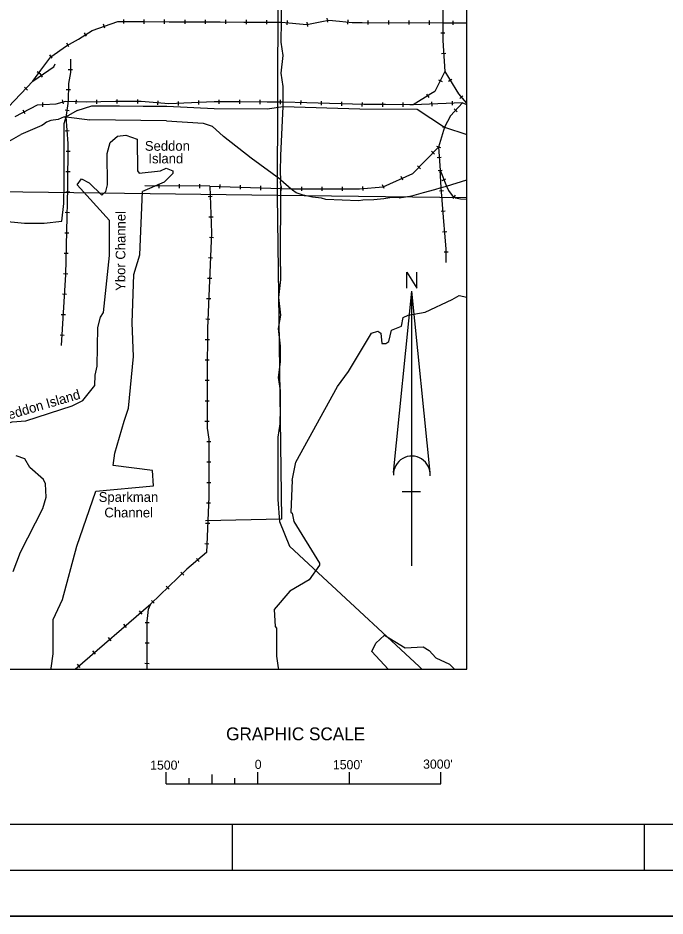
# Model space of a CAD drawing. Extents: x 492225 to 553725, y 1303773 to 1347273.
# Drawn here: x 511586 to 522187, y 1303773 to 1318479 of the extents above; entities that cross this region are included whole.
import ezdxf

# ---------------------------------------------------------------- set-up
doc = ezdxf.new("R2010")
doc.units = 0
for name, color, linetype in [('G-ANNO-TTLB', 7, 'Continuous'), ('Level 1', 7, 'Continuous'), ('Level 2', 7, 'Continuous'), ('Level 22', 7, 'Continuous'), ('Level 37', 7, 'Continuous'), ('Level 41', 7, 'Continuous'), ('Level 5', 7, 'Continuous'), ('Level 52', 7, 'Continuous')]:
    doc.layers.add(name, color=color, linetype=linetype)

msp = doc.modelspace()

# ---------------------------------------------------------------- linework, layer by layer
at = {"layer": 'G-ANNO-TTLB'}
for p, q in [((552225.069, 1305272.564), (494850.069, 1305272.564)), ((515100.069, 1304522.564), (515100.069, 1305272.564)), ((521850.069, 1304522.564), (521850.069, 1305272.564)), ((492975.069, 1304522.564), (552975.069, 1304522.564))]:
    msp.add_line(p, q, dxfattribs=at)
for points in [[(492225.069, 1303772.564), (553725.069, 1303772.564), (553725.069, 1347272.564), (492225.069, 1347272.564)], [(492225.069, 1303772.564), (553725.069, 1303772.564), (553725.069, 1347272.564), (492225.069, 1347272.564)], [(492225.069, 1347272.564), (553725.069, 1347272.564), (553725.069, 1303772.564), (492225.069, 1303772.564)]]:
    msp.add_lwpolyline(points, close=True, dxfattribs=at)
at = {"layer": 'Level 1'}
for p, q in [((515845.848, 1320879.851), (515834.762, 1315574.291)), ((515834.762, 1315574.291), (510479.1, 1315638.587)), ((518939.561, 1315533.3989), (515834.762, 1315574.291)), ((515834.762, 1315574.291), (515901.787, 1310274.027)), ((515901.787, 1310274.027), (514658.533, 1310245.241)), ((514014.882, 1305939.614), (514014.897, 1306127.669)), ((514764.897, 1305939.614), (514764.897, 1306092.989)), ((515514.897, 1305939.614), (515514.882, 1306127.654)), ((515514.897, 1305939.614), (515514.882, 1306127.654)), ((517014.897, 1305939.599), (517014.912, 1306127.654)), ((518514.912, 1305939.599), (518514.897, 1306127.654)), ((514014.882, 1305939.614), (518515.272, 1305939.614)), ((514389.882, 1305943.364), (514389.897, 1306029.614)), ((514764.882, 1305943.364), (514764.882, 1306029.614)), ((515139.897, 1305943.364), (515139.897, 1306029.614)), ((515514.897, 1305939.614), (515514.912, 1306029.599))]:
    msp.add_line(p, q, dxfattribs=at)
at = {"layer": 'Level 2'}
for p, q in [((517739.691, 1311035.137), (518038.191, 1314005.137)), ((518038.191, 1309505.137), (518038.191, 1314005.137)), ((518336.691, 1311035.137), (518038.191, 1314005.137)), ((518180.361, 1310720.377), (517880.376, 1310720.377))]:
    msp.add_line(p, q, dxfattribs=at)
msp.add_lwpolyline([(517955.226, 1314053.272), (517955.226, 1314315.772), (518118.516, 1314053.272), (518118.516, 1314315.772)], dxfattribs=at)
msp.add_arc((518038.1908, 1311005.1371), 300, 355.29842222, 182.06726111, dxfattribs=at)
at = {"layer": 'Level 22'}
for p, q in [((515901.462, 1318410.756), (515902.238, 1318628.886)), ((515900.557, 1318156.271), (515901.283, 1318360.223)), ((515901.283, 1318360.223), (515901.462, 1318410.756)), ((515900.299, 1318083.561), (515900.557, 1318156.271)), ((515931.806, 1317865.317), (515900.299, 1318083.561)), ((515898.489, 1317574.591), (515931.806, 1317865.317)), ((515929.997, 1317356.347), (515898.489, 1317574.591)), ((515929.092, 1317101.863), (515929.997, 1317356.347)), ((512554.316, 1316963.462), (512797.369, 1317040.381)), ((512797.369, 1317040.381), (513249.333, 1317038.744)), ((513249.333, 1317038.744), (513636.73, 1317037.347)), ((513636.73, 1317037.347), (514024.129, 1317035.952)), ((514024.129, 1317035.952), (514798.794, 1316996.819)), ((514798.794, 1316996.819), (515670.439, 1316993.714)), ((515670.439, 1316993.714), (515928.834, 1317029.152)), ((515893.707, 1316229.457), (515928.834, 1317029.152)), ((515928.834, 1317029.152), (515929.092, 1317101.863)), ((515928.834, 1317029.152), (517187.748, 1316988.353)), ((517187.748, 1316988.353), (518123.959, 1316985.073)), ((518123.959, 1316985.073), (518574.909, 1316692.659)), ((512340.857, 1316857.353), (512377.025, 1316860.129)), ((512344.344, 1316751.182), (512377.025, 1316860.129)), ((512554.316, 1316963.462), (512377.025, 1316860.129)), ((512377.025, 1316860.129), (512764.245, 1316809.28)), ((511978.774, 1316719.066), (511633.444, 1316571.996)), ((512343.284, 1316460.342), (512344.344, 1316751.182)), ((514019.379, 1316793.115), (512764.245, 1316809.28)), ((514765.469, 1316706.095), (514953.41, 1316539.643)), ((518574.909, 1316692.659), (518939.561, 1316570.4755)), ((511439.343, 1316463.639), (511633.444, 1316571.996)), ((515406.697, 1316183.198), (514953.41, 1316539.643)), ((512340.767, 1315769.597), (512343.284, 1316460.342)), ((515890.984, 1315826.649), (515406.697, 1316183.198)), ((515886.315, 1315966.271), (515893.707, 1316229.457)), ((515890.984, 1315826.649), (515886.315, 1315966.271)), ((515885.674, 1315785.95), (515890.984, 1315826.649)), ((515890.984, 1315826.649), (516060.929, 1315680.625)), ((518607.702, 1315727.31), (518939.561, 1315826.5473)), ((512339.574, 1315442.402), (512340.767, 1315769.597)), ((515895.778, 1315721.928), (515885.674, 1315785.95)), ((515890.994, 1315466.003), (515891.769, 1315684.133)), ((515891.769, 1315684.133), (515895.778, 1315721.928)), ((518519.797, 1315701.077), (518607.702, 1315727.31)), ((516629.419, 1315508.989), (516561.444, 1315527.617)), ((517165.664, 1315484.771), (516629.419, 1315508.989)), ((512306.229, 1315151.679), (512339.574, 1315442.402)), ((515890.089, 1315211.519), (515890.994, 1315466.003)), ((515889.184, 1314957.034), (515890.089, 1315211.519)), ((511305.404, 1315155.333), (511692.687, 1315117.561)), ((511692.687, 1315117.561), (512015.535, 1315116.383)), ((512015.535, 1315116.383), (512306.229, 1315151.679)), ((515888.28, 1314702.549), (515889.184, 1314957.034)), ((515887.247, 1314411.71), (515888.28, 1314702.549)), ((515887.247, 1314411.71), (515886.471, 1314193.58)), ((515886.471, 1314193.58), (515853.152, 1313902.856)), ((515853.152, 1313902.856), (515884.404, 1313611.902)), ((515884.404, 1313611.902), (515851.343, 1313393.887)), ((515851.343, 1313393.887), (515882.596, 1313102.933)), ((515882.596, 1313102.933), (515881.691, 1312848.448)), ((515881.691, 1312848.448), (515848.5, 1312594.078)), ((515848.5, 1312594.078), (515880.012, 1312375.834)), ((515880.012, 1312375.834), (515878.979, 1312084.995)), ((515878.979, 1312084.995), (515878.074, 1311830.51)), ((515878.074, 1311830.51), (515845.011, 1311612.496)), ((515845.011, 1311612.496), (515844.237, 1311394.367)), ((515844.237, 1311394.367), (515843.849, 1311285.302)), ((515843.849, 1311285.302), (515843.203, 1311103.528)), ((515843.203, 1311103.528), (515842.428, 1310885.398)), ((515842.428, 1310885.398), (515841.781, 1310703.624)), ((515841.781, 1310703.624), (515841.394, 1310594.559)), ((515841.394, 1310594.559), (515872.391, 1310230.896)), ((516579.529, 1309319.512), (518156.631, 1307859.771)), ((518156.631, 1307859.771), (518201.4251, 1307817.676))]:
    msp.add_line(p, q, dxfattribs=at)
for points in [[(512340.857, 1316857.353), (512242.568, 1316816.992), (512123.702, 1316799.973), (512051.28, 1316771.153), (512004.664, 1316736.422), (511978.774, 1316719.066)], [(514019.379, 1316793.115), (514618.434, 1316756.065), (514765.469, 1316706.095)], [(516561.444, 1315527.617), (516411.707, 1315545.597), (516256.845, 1315575.228), (516143.349, 1315616.348), (516081.508, 1315657.284), (516060.929, 1315680.625)], [(517832.197, 1315534.786), (518038.939, 1315568.964), (518230.245, 1315620.649), (518416.385, 1315672.352), (518519.797, 1315701.077)], [(517832.197, 1315534.786), (517713.412, 1315541.018), (517579.027, 1315518.222), (517413.669, 1315501.35), (517238.022, 1315496.15), (517165.664, 1315484.771)], [(515872.391, 1310230.896), (516032.415, 1309830.42), (516579.529, 1309319.512)]]:
    msp.add_lwpolyline(points, dxfattribs=at)
at = {"layer": 'Level 37'}
for p, q in [((513318.309, 1318386.333), (513318.551, 1318453.674)), ((513653.159, 1318385.123), (513653.402, 1318452.466)), ((513988.009, 1318383.919), (513988.252, 1318451.261)), ((514322.86, 1318382.717), (514323.102, 1318450.058)), ((514657.71, 1318381.517), (514657.952, 1318448.858)), ((514992.561, 1318380.319), (514992.803, 1318447.662)), ((515327.412, 1318379.125), (515327.652, 1318446.467)), ((515662.263, 1318377.934), (515662.503, 1318445.276)), ((516665.139, 1318407.758), (516651.826, 1318473.771)), ((516988.219, 1318380.164), (516994.748, 1318447.188)), ((517325.875, 1318372.059), (517326.112, 1318439.401)), ((513007.349, 1318311.232), (512985.532, 1318374.941)), ((515993.821, 1318368.617), (515999.871, 1318435.687)), ((516336.828, 1318341.75), (516323.571, 1318407.774)), ((517660.725, 1318370.888), (517660.962, 1318438.23)), ((517995.576, 1318369.718), (517995.813, 1318437.058)), ((518330.427, 1318368.547), (518330.663, 1318435.888)), ((518715.893, 1318367.202), (518716.128, 1318434.543)), ((512711.094, 1318178.559), (512674.859, 1318235.319)), ((518514.331, 1318234.145), (518581.671, 1318233.911)), ((512421.238, 1318007.243), (512388.411, 1318066.042)), ((512148.137, 1317819.6), (512109.579, 1317874.81)), ((518526.609, 1317897.538), (518593.829, 1317901.566)), ((511955.176, 1317560.346), (511900.42, 1317599.546)), ((511986.881, 1317512.068), (511948.324, 1317567.279)), ((512410.754, 1317637.82), (512478.095, 1317637.576)), ((518578.205, 1317637.888), (518578.079, 1317601.533)), ((511830.337, 1317443.808), (511432.356, 1317023.539)), ((518473.338, 1317466.643), (518533.625, 1317436.64)), ((518637.312, 1317441.355), (518694.629, 1317476.707)), ((511690.766, 1317345.391), (511739.663, 1317299.088)), ((512377.262, 1317305.929), (512444.603, 1317305.684)), ((512332.629, 1317070.595), (512315.277, 1317135.663)), ((512539.352, 1317140.429), (512536.439, 1317073.151)), ((512871.695, 1317137.513), (512873.384, 1317070.192)), ((513207.416, 1317145.278), (513207.172, 1317077.938)), ((513542.266, 1317144.069), (513542.022, 1317076.728)), ((513878.86, 1317120.917), (513873.219, 1317053.813)), ((514543.08, 1317127.971), (514546.132, 1317060.698)), ((514879.317, 1317139.269), (514879.075, 1317071.928)), ((515214.167, 1317138.074), (515213.926, 1317070.733)), ((515549.017, 1317136.883), (515548.777, 1317069.542)), ((515883.867, 1317135.693), (515883.628, 1317068.353)), ((516219.498, 1317126.616), (516217.427, 1317059.306)), ((516554.2, 1317116.24), (516552.108, 1317048.932)), ((518280.569, 1317232.219), (518315.639, 1317174.73)), ((518698.171, 1317118.244), (518700.967, 1317050.961)), ((518826.625, 1317159.26), (518877.134, 1317203.8)), ((511701.899, 1316909.996), (511671.037, 1316969.849)), ((511995.572, 1317026), (511991.289, 1317093.206)), ((514208.571, 1317112.794), (514211.623, 1317045.522)), ((516888.892, 1317105.832), (516886.798, 1317038.523)), ((517223.582, 1317095.424), (517221.489, 1317028.115)), ((517557.49, 1317093.437), (517557.254, 1317026.096)), ((517892.34, 1317092.265), (517892.104, 1317024.924)), ((518866.851, 1317091.554), (518059.648, 1317058.009)), ((518363.607, 1317104.341), (518366.403, 1317037.058)), ((518730.147, 1316989.194), (518780.344, 1316944.304)), ((512425.718, 1316956.809), (512359.141, 1316966.928)), ((518541.337, 1316697.928), (518605.842, 1316678.589)), ((512426.889, 1316631.108), (512359.713, 1316626.382)), ((512440.919, 1316294.274), (512373.579, 1316294.518)), ((518411.331, 1316249.71), (518362.964, 1316296.566)), ((518445.176, 1316377.177), (518509.681, 1316357.838)), ((518476.917, 1316365.802), (518501.421, 1315986.53)), ((518454.111, 1316196.552), (518521.312, 1316200.894)), ((512439.699, 1315959.421), (512372.358, 1315959.666)), ((518178.339, 1316009.204), (518129.973, 1316056.061)), ((518535.574, 1315980.131), (518468.371, 1315975.804)), ((517892.847, 1315821.463), (517865.406, 1315882.959)), ((518533.781, 1315818.845), (518596.089, 1315844.392)), ((514729.667, 1315724.627), (513664.288, 1315728.451)), ((513892.662, 1315761.303), (513892.419, 1315693.96)), ((514227.512, 1315760.1), (514227.269, 1315692.758)), ((514562.363, 1315758.898), (514562.12, 1315691.557)), ((514895.819, 1315685.145), (514898.164, 1315752.447)), ((515230.469, 1315673.484), (515232.814, 1315740.786)), ((515565.118, 1315661.823), (515567.463, 1315729.125)), ((515900.245, 1315650.278), (515901.642, 1315717.607)), ((516235.847, 1315647.403), (516235.674, 1315714.744)), ((516570.494, 1315648.061), (516570.732, 1315715.402)), ((516905.344, 1315646.881), (516905.582, 1315714.223)), ((517243.11, 1315651.182), (517237.054, 1315718.251)), ((517587.058, 1315685.008), (517559.616, 1315746.505)), ((518557.915, 1315646.538), (518490.786, 1315641.194)), ((512436.829, 1315623.827), (512369.512, 1315625.604)), ((514702.495, 1315556.021), (514769.787, 1315558.626)), ((518715.724, 1315521.947), (518752.114, 1315578.61)), ((512427.987, 1315289.088), (512360.669, 1315290.865)), ((514715.444, 1315221.417), (514782.735, 1315224.021)), ((518584.484, 1315312.738), (518517.356, 1315307.394)), ((512419.144, 1314954.349), (512351.827, 1314956.127)), ((518611.005, 1314978.926), (518543.875, 1314973.601)), ((514722.305, 1314889.643), (514789.579, 1314886.623)), ((512410.302, 1314619.61), (512342.984, 1314621.388)), ((518633.717, 1314642.206), (518566.375, 1314642.44)), ((514707.287, 1314555.124), (514774.56, 1314552.105)), ((512401.459, 1314284.872), (512334.142, 1314286.649)), ((514692.269, 1314220.606), (514759.542, 1314217.587)), ((512381.86, 1313949.492), (512314.637, 1313953.468)), ((514677.25, 1313886.088), (514744.524, 1313883.067)), ((512362.084, 1313615.221), (512294.861, 1313619.197)), ((514662.232, 1313551.569), (514729.505, 1313548.549)), ((512342.309, 1313280.949), (512275.084, 1313284.926)), ((514654.718, 1313215.478), (514722.059, 1313215.238)), ((514653.519, 1312880.625), (514720.859, 1312880.384)), ((514652.318, 1312545.772), (514719.659, 1312545.531)), ((514651.118, 1312210.918), (514718.459, 1312210.678)), ((514649.919, 1311876.065), (514717.259, 1311875.824)), ((514681.016, 1311543.942), (514748.356, 1311543.702)), ((514679.816, 1311209.088), (514747.157, 1311208.848)), ((514678.617, 1310874.235), (514745.958, 1310873.995)), ((514674.045, 1310540.65), (514741.336, 1310538.018)), ((514660.959, 1310206.05), (514728.248, 1310203.419)), ((514647.87, 1309871.451), (514715.16, 1309868.819)), ((514508.761, 1309628.178), (514552.402, 1309576.892)), ((514256.284, 1309405.391), (514302.873, 1309356.766)), ((514014.499, 1309173.728), (514061.089, 1309125.103)), ((512520.748, 1307817.676), (513763.26, 1308886.373)), ((513772.714, 1308942.063), (513819.303, 1308893.438)), ((513619.002, 1308717.884), (513575.091, 1308768.939)), ((513365.134, 1308499.529), (513321.222, 1308550.583)), ((513736.717, 1308574.809), (513669.376, 1308575.053)), ((513111.266, 1308281.174), (513067.354, 1308332.229)), ((513735.509, 1308239.957), (513668.168, 1308240.199)), ((512857.398, 1308062.819), (512813.485, 1308113.874)), ((512603.529, 1307844.465), (512559.618, 1307895.52)), ((513734.302, 1307905.103), (513666.96, 1307905.346))]:
    msp.add_line(p, q, dxfattribs=at)
for points in [[(518549.474, 1318655.94), (518548.585, 1318401.455)], [(511830.337, 1317443.808), (511960.133, 1317625.113), (512122.342, 1317842.654), (512381.265, 1318023.489), (512575.356, 1318131.851), (512801.86, 1318276.45), (513222.055, 1318420.351), (513641.721, 1318418.836), (514061.388, 1318417.326), (514448.771, 1318415.936), (514900.719, 1318414.319), (515288.104, 1318412.936), (515675.489, 1318411.558), (515901.462, 1318410.756), (516320.999, 1318372.914), (516566.519, 1318422.218), (516676.359, 1318444.37), (516854.496, 1318427.018), (517063.614, 1318406.651), (517225.024, 1318406.083), (518548.585, 1318401.455)], [(518548.585, 1318401.455), (518547.571, 1318110.615), (518578.079, 1317601.533)], [(518548.585, 1318401.455), (518939.561, 1318400.0967)], [(511830.337, 1317443.808), (512089.264, 1317624.642), (512131.967, 1317649.208), (512173.395, 1317678.142), (512194.246, 1317730.418)], [(512445.035, 1317805.124), (512444.24, 1317586.994), (512411.295, 1317405.337), (512410.228, 1317112.315)], [(518578.079, 1317601.533), (518415.522, 1317274.901), (518348.231, 1317234.053), (518059.648, 1317058.009)], [(518578.079, 1317601.533), (518757.849, 1317310.065), (518802.791, 1317237.198), (518931.417, 1317091.33)], [(511537.659, 1316863.189), (511908.006, 1317054.158), (511999.714, 1317060.003), (512212.511, 1317073.408), (512345.649, 1317108.914), (512369.562, 1317115.372), (512410.228, 1317112.315)], [(512298.809, 1313115.802), (512367.62, 1314278.927), (512405.071, 1315696.653), (512407.719, 1316423.752), (512377.025, 1316860.129), (512380.996, 1316886.654), (512410.104, 1317078.142), (512410.228, 1317112.315)], [(518059.648, 1317058.009), (518006.38, 1317058.195), (517607.684, 1317059.59), (517252.569, 1317060.835), (516316.452, 1317089.947), (515929.092, 1317101.863), (515670.828, 1317102.779), (515226.935, 1317104.358), (514896.034, 1317105.538), (514799.184, 1317105.885), (514056.543, 1317072.191), (513604.71, 1317110.173), (513185.03, 1317111.688), (512703.639, 1317099.617), (512410.228, 1317112.315)], [(518866.851, 1317091.554), (518672.392, 1316874.097), (518574.909, 1316692.659), (518476.917, 1316365.802)], [(518866.851, 1317091.554), (518939.561, 1317063.9721)], [(514729.667, 1315724.627), (515891.769, 1315684.133), (516060.929, 1315680.625), (516537.454, 1315681.848), (516559.408, 1315681.771), (517183.139, 1315679.574), (517570.677, 1315714.569), (518055.703, 1315931.006), (518476.917, 1316365.802)], [(518501.421, 1315986.53), (518607.702, 1315727.31), (518640.374, 1315653.395), (518698.208, 1315573.212), (518756.834, 1315535.563), (518837.478, 1315515.651), (518934.955, 1315509.495), (518939.561, 1315509.2535)], [(518599.463, 1314474.897), (518600.223, 1314693.026), (518578.561, 1314962.13), (518564.026, 1315145.412), (518519.797, 1315701.077), (518501.421, 1315986.53)], [(514729.667, 1315724.627), (514759.216, 1314961.058), (514689.043, 1313398.026), (514686.307, 1312634.573), (514683.441, 1311834.764), (514683.18, 1311762.054), (514714.816, 1311580.164), (514714.035, 1311362.035), (514713.123, 1311107.551), (514712.212, 1310853.067), (514711.429, 1310634.938), (514675.885, 1309726.181), (514352.972, 1309451.399), (513763.26, 1308886.373)], [(513700.3148, 1307817.676), (513703.146, 1308602.654), (513713.162, 1308693.871), (513724.184, 1308795.262), (513763.26, 1308886.373)]]:
    msp.add_lwpolyline(points, dxfattribs=at)
at = {"layer": 'Level 5'}
for points in [[(512938.391, 1313578.837), (512988.64, 1313653.698), (513083.079, 1314586.863), (513084.808, 1315161.936), (512553.169, 1315746.933), (512628.478, 1315846.714), (512753.298, 1315779.655), (512961.037, 1315579.027), (513027.887, 1315637.158), (513053.227, 1315745.428), (513046.436, 1316262.18), (513096.975, 1316437.062), (513213.954, 1316545.053), (513355.714, 1316561.315), (513538.864, 1316494.067), (513545.654, 1315977.314), (513570.504, 1315935.584), (513920.683, 1315976.218), (514012.483, 1316017.599), (514120.722, 1315975.63), (514120.562, 1315933.949), (513978.463, 1315792.678), (513627.954, 1315635.383)], [(513454.839, 1313485.612), (513482.228, 1314277.286), (513583.197, 1314602.048), (513627.954, 1315635.383)], [(517897.302, 1313572.366), (517979.246, 1313613.543), (518257.926, 1313660.016), (518697.382, 1313866.155), (518815.158, 1313936.337), (518939.561, 1313908.9071)], [(512852.213, 1312628.962), (512886.003, 1312778.903), (512896.211, 1313412.286), (512938.391, 1313578.837)], [(512863.206, 1310728.703), (513805.233, 1310817.563), (513789.303, 1311067.634), (513147.834, 1311152.918), (513173.434, 1311352.859), (513327.041, 1311876.715), (513395.55, 1312091.4), (513478.21, 1312935.489), (513454.839, 1313485.612)], [(516080.754, 1310902.446), (516139.984, 1311202.328), (516818.789, 1312442.13), (517002.898, 1312691.613), (517379.804, 1313315.56), (517479.904, 1313348.601), (517529.824, 1313315.121), (517545.994, 1313148.361), (517612.674, 1313148.181), (517662.764, 1313181.342), (517704.974, 1313364.593), (517871.883, 1313430.765), (517897.302, 1313572.366)], [(508324.051, 1311750.713), (508382.121, 1311658.884), (508498.541, 1311575.174), (509205.919, 1311223.01), (509455.928, 1311222.273), (510732.503, 1311693.517), (511116.011, 1311742.371), (511491.429, 1311866.265), (511716.499, 1311882.288), (512475.665, 1312130.036), (512650.934, 1312212.848), (512843.374, 1312462.331), (512852.213, 1312628.962)], [(511509.114, 1309415.904), (511626.723, 1309732.277), (511995.59, 1310447.933), (512046.139, 1310631.155), (512038.459, 1310847.856), (512005.329, 1310922.956), (511780.879, 1311115.334), (511697.949, 1311257.264), (511556.44, 1311307.693)], [(516080.754, 1310902.446), (516054.205, 1310385.813), (516079.145, 1310369.053), (516103.765, 1310235.643), (516526.745, 1309550.943), (516526.655, 1309517.603), (516359.246, 1309276.431), (516041.998, 1309094.017), (515782.729, 1308794.733), (515798.559, 1308511.322), (515823.479, 1308486.262), (515822.11, 1308027.879), (515846.551, 1307836.089), (515856.589, 1307817.676)], [(512128.9376, 1307817.676), (512129.424, 1307830.553), (512163.444, 1308063.814), (512165.143, 1308630.547), (512316.152, 1308955.12), (512552.139, 1309829.527), (512863.206, 1310728.703)], [(517650.0745, 1307817.676), (517380.875, 1308106.555), (517447.944, 1308239.706), (517590.014, 1308372.618), (517931.123, 1308163.241), (518222.862, 1308179.043), (518322.701, 1308120.404), (518430.691, 1308003.394), (518655.371, 1307894.386), (518736.8868, 1307817.676)]]:
    msp.add_lwpolyline(points, dxfattribs=at)
at = {"layer": 'Level 52'}
msp.add_lwpolyline([(518939.5614, 1342691.8404), (495463.7934, 1342691.8404), (495463.7934, 1307817.676), (518939.5614, 1307817.676)], close=True, dxfattribs=at)

# ---------------------------------------------------------------- texts
at = {"layer": 'Level 1'}
for s, height, p in [('GRAPHIC SCALE', 209.99988, (514996.242, 1306650.764)), ("1500'", 149.99994, (513752.245, 1306168.919)), ('0', 149.9984, (515465.202, 1306181.009)), ("1500'", 149.99994, (516746.215, 1306175.699)), ("3000'", 149.99994, (518223.94, 1306185.314))]:
    msp.add_text(s, height=height, dxfattribs=at).set_placement(p)
at = {"layer": 'Level 41'}
for s, p in [('Seddon', (513664.705, 1316304.373)), ('Island', (513722.035, 1316097.753)), ('Sparkman', (512908.573, 1310554.766)), ('Channel', (513001.297, 1310300.463))]:
    msp.add_text(s, height=160, dxfattribs=at).set_placement(p)
for s, rotation, p in [('Ybor Channel', 89.79208891, (513343.94, 1314009.293)), ('Seddon Island', 16.37247494, (511308.194, 1311862.077))]:
    msp.add_text(s, height=159.999996, rotation=rotation, dxfattribs=at).set_placement(p)

doc.saveas('drawing.dxf')
